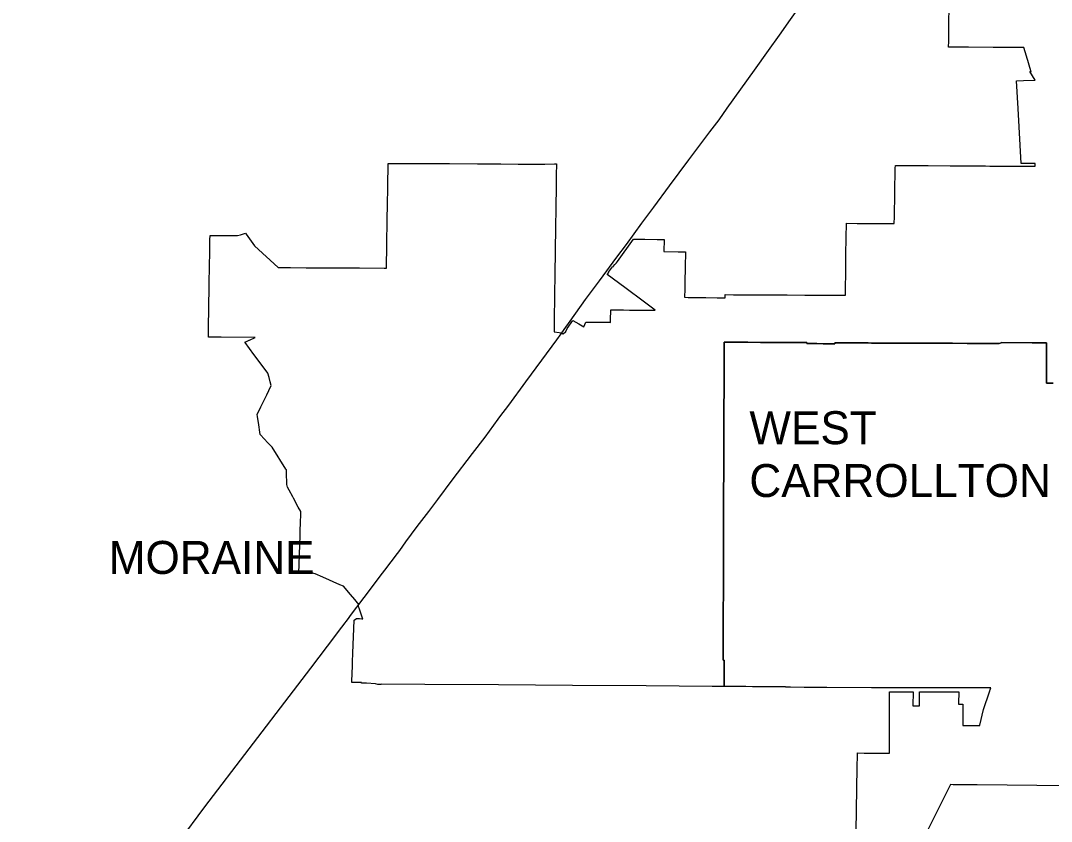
# Model space of a CAD drawing. Extents: x 0 to 34, y 0 to 22.
# Drawn here: x 4.6743 to 4.9254, y 14.6404 to 14.8356 of the extents above; entities that cross this region are included whole.
import ezdxf

# ---------------------------------------------------------------- set-up
doc = ezdxf.new("R2010")
doc.units = 0
for name, color, linetype in [('GM_X_Corporation', 7, 'Continuous'), ('GM_X_Corporation_Text', 7, 'Continuous'), ('GM_X_State_Route', 7, 'Continuous')]:
    doc.layers.add(name, color=color, linetype=linetype)

msp = doc.modelspace()

# ---------------------------------------------------------------- linework, layer by layer
at = {"layer": 'GM_X_Corporation'}
for points in [[(4.92583, 14.74721), (4.92421, 14.74722), (4.92422, 14.74919), (4.92422, 14.75086), (4.92424, 14.75703), (4.92407, 14.75704), (4.92339, 14.75704), (4.92068, 14.75706), (4.9133, 14.75711), (4.91316, 14.75706), (4.91294, 14.75698), (4.91267, 14.75688), (4.91235, 14.75688), (4.91199, 14.75688), (4.90488, 14.75692), (4.90131, 14.75694), (4.89991, 14.75695), (4.89758, 14.75696), (4.89686, 14.75697), (4.89432, 14.75698), (4.89201, 14.75699), (4.88927, 14.75699), (4.88879, 14.75699), (4.88853, 14.75699), (4.88643, 14.75699), (4.88547, 14.75699), (4.8845, 14.757), (4.88354, 14.75701), (4.88257, 14.75701), (4.88161, 14.75702), (4.88072, 14.75703), (4.88065, 14.75703), (4.87968, 14.75703), (4.87872, 14.75704), (4.87775, 14.75705), (4.87679, 14.75705), (4.87642, 14.75705), (4.87481, 14.75707), (4.8726, 14.75708), (4.8726, 14.75684), (4.87179, 14.75684), (4.86998, 14.75685), (4.86981, 14.75685), (4.86825, 14.75686), (4.86821, 14.75686), (4.86695, 14.75687), (4.8658, 14.75688), (4.8658, 14.75712), (4.86489, 14.75712), (4.86212, 14.75714), (4.86087, 14.75714), (4.8545, 14.75717), (4.85145, 14.75719), (4.84793, 14.75721), (4.84571, 14.75722), (4.8457, 14.7553), (4.84567, 14.74942), (4.84566, 14.74685), (4.84563, 14.74012), (4.84562, 14.73729), (4.84561, 14.73592), (4.84561, 14.73456), (4.84561, 14.73437), (4.8456, 14.7327), (4.84558, 14.72946), (4.84557, 14.72612), (4.84556, 14.72393), (4.84555, 14.72218), (4.84555, 14.72157), (4.84555, 14.72051), (4.84554, 14.71961), (4.84553, 14.71575), (4.84552, 14.71505), (4.84552, 14.71398), (4.84552, 14.71151), (4.84549, 14.70176), (4.84548, 14.69803), (4.84548, 14.69777), (4.8454, 14.69027), (4.8454, 14.69019), (4.84542, 14.68603), (4.84542, 14.68554), (4.84544, 14.6835), (4.84544, 14.68264), (4.84546, 14.68058), (4.84546, 14.67975), (4.8457, 14.67975), (4.84569, 14.67782), (4.84568, 14.67589), (4.84566, 14.67362), (4.84566, 14.67359), (4.84566, 14.67358), (4.84566, 14.67357), (4.84566, 14.67356), (4.84566, 14.6733), (4.84273, 14.67332), (4.82665, 14.67343), (4.80869, 14.67356), (4.79068, 14.67368), (4.77271, 14.67381), (4.76209, 14.67388), (4.76208, 14.6738), (4.76127, 14.67381), (4.76074, 14.67397), (4.76074, 14.67397), (4.7585, 14.67409), (4.7573, 14.67411), (4.7573, 14.67424), (4.75493, 14.67428), (4.75504, 14.67678), (4.75505, 14.67714), (4.75508, 14.67772), (4.7551, 14.67817), (4.75512, 14.67864), (4.75513, 14.67891), (4.75514, 14.67931), (4.75522, 14.68144), (4.75553, 14.68946), (4.75607, 14.68989), (4.75647, 14.68987), (4.75682, 14.68985), (4.75743, 14.68982), (4.7576, 14.68981), (4.75747, 14.69021), (4.75688, 14.69193), (4.75649, 14.69307), (4.75668, 14.69332), (4.75566, 14.69451), (4.75466, 14.69569), (4.75292, 14.69772), (4.75201, 14.69812), (4.74788, 14.69992), (4.74603, 14.70073), (4.74572, 14.70087), (4.74532, 14.70104), (4.74496, 14.7012), (4.74454, 14.70138), (4.74439, 14.70135), (4.74207, 14.70087), (4.74233, 14.71012), (4.74236, 14.71094), (4.74237, 14.71128), (4.74238, 14.71176), (4.74241, 14.71282), (4.74249, 14.71575), (4.7425, 14.71593), (4.74191, 14.71704), (4.74073, 14.71923), (4.74056, 14.71954), (4.73971, 14.72114), (4.73931, 14.72187), (4.73909, 14.72254), (4.73903, 14.72548), (4.73902, 14.72608), (4.73888, 14.72628), (4.73551, 14.73162), (4.7344, 14.73279), (4.73368, 14.73356), (4.73261, 14.7347), (4.73218, 14.73766), (4.73198, 14.73902), (4.73197, 14.73909), (4.7319, 14.73956), (4.73282, 14.74148), (4.73423, 14.7444), (4.73473, 14.74546), (4.73532, 14.74664), (4.73506, 14.74757), (4.73478, 14.7486), (4.73448, 14.74966), (4.73118, 14.75413), (4.7311, 14.75423), (4.72893, 14.75718), (4.7289, 14.75722), (4.72903, 14.75728), (4.7293, 14.75741), (4.72996, 14.75771), (4.73002, 14.75774), (4.73139, 14.75837), (4.72313, 14.75844), (4.72171, 14.75845), (4.72003, 14.75847), (4.72002, 14.75885), (4.72002, 14.75895), (4.72002, 14.75915), (4.72003, 14.75927), (4.72002, 14.75927), (4.72015, 14.76711), (4.72018, 14.76929), (4.72023, 14.77266), (4.72026, 14.77462), (4.72028, 14.77558), (4.72033, 14.7793), (4.72036, 14.78067), (4.72038, 14.78196), (4.72038, 14.78218), (4.7204, 14.78326), (4.72449, 14.78322), (4.7269, 14.7832), (4.72713, 14.78319), (4.72781, 14.7834), (4.72905, 14.78378), (4.72924, 14.78352), (4.73124, 14.78074), (4.73697, 14.77542), (4.73731, 14.77542), (4.73999, 14.7754), (4.74385, 14.77536), (4.74498, 14.77536), (4.74737, 14.77535), (4.74962, 14.77535), (4.75353, 14.77534), (4.7561, 14.77533), (4.75679, 14.77532), (4.76286, 14.77523), (4.76341, 14.77523), (4.76341, 14.77544), (4.76344, 14.77776), (4.76345, 14.77848), (4.76345, 14.77883), (4.76351, 14.78231), (4.76357, 14.78575), (4.76358, 14.78656), (4.76366, 14.79134), (4.7637, 14.79424), (4.76372, 14.79518), (4.7638, 14.80078), (4.76403, 14.80078), (4.76496, 14.80078), (4.7701, 14.80077), (4.77253, 14.80076), (4.7766, 14.80076), (4.77875, 14.80076), (4.78555, 14.8007), (4.78877, 14.80067), (4.79125, 14.80065), (4.79545, 14.80061), (4.79691, 14.8006), (4.80196, 14.80064), (4.8043, 14.80067), (4.80481, 14.80067), (4.80477, 14.79795), (4.80474, 14.7958), (4.80473, 14.79539), (4.80465, 14.78982), (4.80458, 14.78528), (4.80442, 14.7737), (4.8044, 14.77224), (4.80437, 14.77033), (4.80434, 14.76826), (4.80431, 14.76618), (4.80429, 14.76505), (4.80429, 14.7649), (4.80427, 14.76359), (4.80425, 14.76224), (4.80422, 14.75974), (4.80551, 14.75959), (4.80606, 14.75952), (4.80646, 14.75925), (4.8071, 14.75986), (4.80743, 14.76059), (4.80884, 14.76254), (4.81028, 14.76168), (4.81151, 14.76095), (4.81198, 14.76211), (4.81719, 14.76206), (4.81779, 14.76206), (4.818, 14.76205), (4.81801, 14.76258), (4.81806, 14.7651), (4.81958, 14.76509), (4.82072, 14.76508), (4.82111, 14.76507), (4.82263, 14.76506), (4.82407, 14.76505), (4.82415, 14.76504), (4.82492, 14.76504), (4.82568, 14.76503), (4.82611, 14.76503), (4.82683, 14.76502), (4.8272, 14.76502), (4.8289, 14.765), (4.82628, 14.76695), (4.82149, 14.77051), (4.81719, 14.7737), (4.81757, 14.77422), (4.8175, 14.77427), (4.81846, 14.77556), (4.81852, 14.77551), (4.81863, 14.77566), (4.819, 14.77616), (4.81942, 14.77658), (4.8197, 14.77685), (4.82355, 14.78235), (4.82635, 14.78231), (4.82936, 14.78228), (4.83022, 14.78227), (4.83105, 14.78226), (4.83098, 14.77935), (4.83444, 14.77925), (4.83625, 14.7792), (4.83617, 14.77551), (4.83609, 14.77181), (4.83606, 14.77015), (4.83602, 14.76816), (4.83691, 14.76814), (4.8371, 14.76814), (4.84124, 14.76808), (4.84396, 14.76804), (4.84524, 14.76803), (4.84588, 14.76802), (4.84589, 14.76881), (4.84793, 14.7688), (4.85049, 14.76878), (4.85112, 14.76878), (4.85361, 14.76876), (4.85544, 14.76875), (4.8565, 14.76875), (4.86038, 14.76872), (4.86104, 14.76872), (4.86533, 14.7687), (4.86633, 14.76869), (4.87027, 14.76867), (4.87135, 14.76866), (4.87524, 14.76864), (4.87527, 14.77054), (4.87532, 14.77394), (4.87533, 14.77462), (4.87533, 14.77613), (4.87532, 14.77709), (4.87531, 14.77859), (4.87538, 14.78262), (4.87545, 14.7862), (4.87806, 14.78618), (4.87894, 14.78618), (4.8805, 14.78617), (4.88058, 14.78617), (4.88229, 14.78616), (4.88434, 14.78615), (4.88712, 14.78613), (4.88715, 14.78779), (4.88718, 14.78944), (4.88722, 14.7919), (4.88724, 14.79275), (4.88725, 14.79364), (4.88736, 14.79962), (4.88738, 14.80032), (4.8887, 14.80031), (4.88906, 14.80031), (4.88918, 14.80031), (4.89364, 14.80027), (4.89541, 14.80025), (4.90074, 14.8002), (4.90109, 14.8002), (4.90664, 14.80017), (4.90937, 14.80016), (4.91037, 14.80015), (4.91193, 14.80014), (4.91448, 14.80013), (4.91925, 14.8001), (4.92142, 14.80009), (4.92147, 14.80009), (4.92145, 14.8004), (4.92144, 14.80074), (4.9214, 14.80074), (4.91973, 14.80074), (4.91821, 14.80075), (4.91807, 14.80075), (4.91781, 14.80524), (4.91728, 14.81421), (4.91689, 14.8209), (4.91695, 14.82091), (4.91861, 14.82096), (4.92147, 14.82105), (4.92013, 14.82321), (4.92051, 14.82314), (4.91992, 14.825), (4.91991, 14.82504), (4.91867, 14.82906), (4.91468, 14.82906), (4.91206, 14.82907), (4.91119, 14.82907), (4.90519, 14.82908), (4.9047, 14.82908), (4.90084, 14.82908), (4.90036, 14.82908), (4.90038, 14.83058), (4.90043, 14.8336), (4.90045, 14.83504), (4.90056, 14.84259)], [(4.87787, 14.63804), (4.8781, 14.6536), (4.87815, 14.65664), (4.87815, 14.6571), (4.87976, 14.65709), (4.88389, 14.65707), (4.88552, 14.65706), (4.88593, 14.65706), (4.88593, 14.6574), (4.88594, 14.659), (4.88595, 14.66199), (4.88599, 14.67201), (4.89121, 14.67199), (4.8917, 14.67199), (4.89165, 14.66858), (4.89165, 14.66856), (4.89326, 14.66856), (4.8933, 14.67199), (4.8941, 14.67199), (4.90007, 14.67201), (4.9016, 14.67201), (4.90283, 14.67201), (4.9028, 14.66919), (4.9028, 14.669), (4.90382, 14.66901), (4.90382, 14.66864), (4.90382, 14.66573), (4.90381, 14.66376), (4.90494, 14.66376), (4.90793, 14.66376), (4.90799, 14.66389), (4.90885, 14.6677), (4.91033, 14.67202), (4.91032, 14.67202), (4.91041, 14.67226), (4.91044, 14.67235), (4.91049, 14.6725), (4.91065, 14.67298), (4.91019, 14.67298), (4.90791, 14.67299), (4.90171, 14.67298), (4.90009, 14.67297), (4.89444, 14.67296), (4.89294, 14.67295), (4.89281, 14.67295), (4.88515, 14.67298), (4.88338, 14.67298), (4.88161, 14.67299), (4.87072, 14.67305), (4.86748, 14.67308), (4.86558, 14.67309), (4.86516, 14.67309), (4.86183, 14.67311), (4.86059, 14.67312), (4.86059, 14.6732), (4.85898, 14.67321), (4.85738, 14.67322), (4.85577, 14.67323), (4.85416, 14.67325), (4.85255, 14.67326), (4.85095, 14.67327), (4.84894, 14.67328), (4.84595, 14.6733), (4.84566, 14.6733), (4.84566, 14.67356), (4.84566, 14.67358), (4.84566, 14.67359), (4.84566, 14.6736), (4.84566, 14.67361), (4.84566, 14.67362), (4.84568, 14.67589), (4.84569, 14.67782), (4.8457, 14.67975), (4.84546, 14.67975), (4.84546, 14.68058), (4.84544, 14.68264), (4.84544, 14.6835), (4.84542, 14.68554), (4.84542, 14.68603), (4.8454, 14.69019), (4.8454, 14.69027), (4.84548, 14.69777), (4.84548, 14.69803), (4.84549, 14.70176), (4.84549, 14.7019), (4.84552, 14.71151), (4.84552, 14.71398), (4.84552, 14.71505), (4.84553, 14.71575), (4.84554, 14.71961), (4.84555, 14.72051), (4.84555, 14.72157), (4.84555, 14.72218), (4.84556, 14.72393), (4.84557, 14.72612), (4.84558, 14.72946), (4.8456, 14.73251), (4.8456, 14.7327), (4.84561, 14.73437), (4.84561, 14.73456), (4.84561, 14.73592), (4.84562, 14.7372), (4.84562, 14.73729), (4.84563, 14.74012), (4.84566, 14.74685), (4.84567, 14.74942), (4.8457, 14.7553), (4.84571, 14.75722), (4.84793, 14.75721), (4.85145, 14.75719), (4.8545, 14.75717), (4.86087, 14.75714), (4.86212, 14.75714), (4.86489, 14.75712), (4.8658, 14.75712), (4.8658, 14.75688), (4.86695, 14.75687), (4.86821, 14.75686), (4.86981, 14.75685), (4.86998, 14.75685), (4.87179, 14.75684), (4.8726, 14.75684), (4.8726, 14.75708), (4.87481, 14.75707), (4.87642, 14.75705), (4.87679, 14.75705), (4.87775, 14.75705), (4.87872, 14.75704), (4.87968, 14.75703), (4.88065, 14.75703), (4.88161, 14.75702), (4.88257, 14.75701), (4.88354, 14.75701), (4.8845, 14.757), (4.88547, 14.75699), (4.88643, 14.75699), (4.88853, 14.75699), (4.88879, 14.75699), (4.88927, 14.75699), (4.89201, 14.75699), (4.89432, 14.75698), (4.89686, 14.75697), (4.89758, 14.75696), (4.89991, 14.75695), (4.90131, 14.75694), (4.90488, 14.75692), (4.91199, 14.75688), (4.91235, 14.75688), (4.91267, 14.75688), (4.91294, 14.75698), (4.91316, 14.75706), (4.9133, 14.75711), (4.92068, 14.75706), (4.92339, 14.75704), (4.92407, 14.75704), (4.92424, 14.75703), (4.92422, 14.75086), (4.92422, 14.74919), (4.92421, 14.74722), (4.92583, 14.74721)], [(4.9292, 14.64913), (4.90734, 14.64933), (4.90203, 14.64938), (4.9019, 14.64938), (4.90144, 14.64938), (4.90085, 14.64939), (4.88706, 14.62196)]]:
    msp.add_lwpolyline(points, dxfattribs=at)
at = {"layer": 'GM_X_State_Route'}
msp.add_line((4.80491, 14.75776), (4.80593, 14.75923), dxfattribs=at)
for points in [[(4.84637, 14.81423), (4.85306, 14.8235), (4.85647, 14.82828), (4.85914, 14.83206), (4.86186, 14.83588), (4.86711, 14.84334), (4.86762, 14.84403)], [(4.80593, 14.75923), (4.80669, 14.76028), (4.80816, 14.76235), (4.81191, 14.76759), (4.81531, 14.77216), (4.81954, 14.77793), (4.82184, 14.78104), (4.82565, 14.78623), (4.82852, 14.79009), (4.83235, 14.79531), (4.83707, 14.80166), (4.8422, 14.80846), (4.84443, 14.8114), (4.84637, 14.81423)], [(4.79105, 14.739), (4.79319, 14.74187), (4.79733, 14.74752), (4.80126, 14.75282), (4.80491, 14.75776)], [(4.77542, 14.71826), (4.77589, 14.71888), (4.77942, 14.72358), (4.78437, 14.73009), (4.7874, 14.73411), (4.79064, 14.73845), (4.79105, 14.739)], [(4.76661, 14.70649), (4.76815, 14.70854), (4.77091, 14.7123), (4.77371, 14.71599), (4.77542, 14.71826)], [(4.76296, 14.70164), (4.76605, 14.70573), (4.76661, 14.70649)], [(4.75442, 14.6903), (4.75792, 14.69496), (4.76244, 14.70095), (4.76296, 14.70164)], [(4.74179, 14.67361), (4.74496, 14.67774), (4.74906, 14.68311), (4.75253, 14.68773), (4.75437, 14.69023), (4.75442, 14.6903)], [(4.67425, 14.58751), (4.67767, 14.59166), (4.69056, 14.6072), (4.6927, 14.6097), (4.69743, 14.6154), (4.70004, 14.61862), (4.70413, 14.62384), (4.70902, 14.63035), (4.71286, 14.63549), (4.71914, 14.64394), (4.74073, 14.67225), (4.74179, 14.67361)]]:
    msp.add_lwpolyline(points, dxfattribs=at)

# ---------------------------------------------------------------- texts
at = {"layer": 'GM_X_Corporation_Text'}
for s, p in [('WEST', (4.85181, 14.73236)), ('CARROLLTON', (4.85181, 14.71948)), ('MORAINE', (4.69572, 14.70074))]:
    msp.add_text(s, height=0.008037, rotation=0, dxfattribs=at).set_placement(p)

doc.saveas('drawing.dxf')
